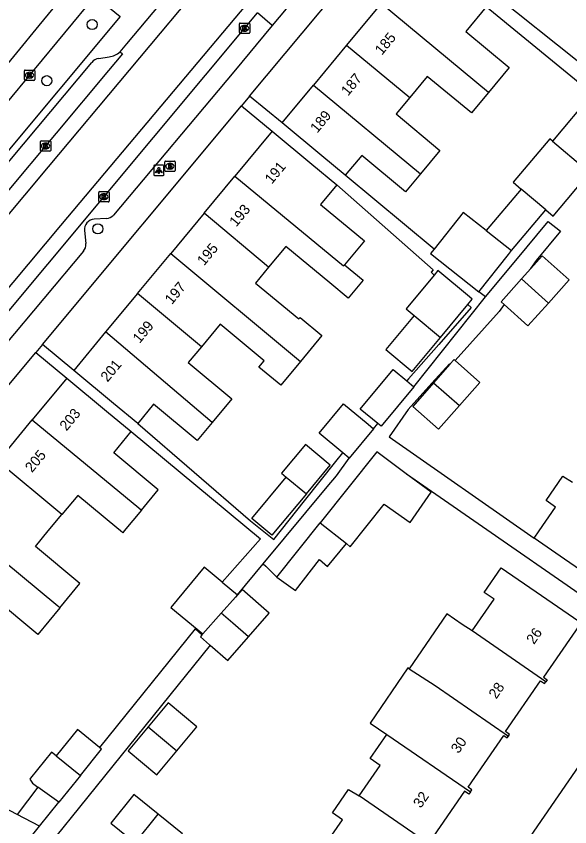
# Model space of a CAD drawing. Extents: x 160158 to 160921, y 381517 to 382041.
# Drawn here: x 160578.4 to 160631.9, y 381721.4 to 381799.8 of the extents above; entities that cross this region are included whole.
import ezdxf

# ---------------------------------------------------------------- set-up
doc = ezdxf.new("R2010")
doc.units = 0
for name, color, linetype in [('IMGEO_Boom', 7, 'Continuous'), ('IMGEO_Brandkraan', 7, 'Continuous'), ('IMGEO_Kolk', 7, 'Continuous'), ('IMGEO_Lichtpunt', 7, 'Continuous'), ('IMGEO_Pand', 7, 'Continuous'), ('IMGEO_Pand_nummerreeks', 7, 'Continuous'), ('IMGEO_Parkeervlak_open', 7, 'Continuous'), ('IMGEO_Rijbaan_lokaal_gesloten', 7, 'Continuous'), ('IMGEO_Voetpad_open', 7, 'Continuous')]:
    doc.layers.add(name, color=color, linetype=linetype)

msp = doc.modelspace()

# ---------------------------------------------------------------- linework, layer by layer
at = {"layer": 'IMGEO_Boom'}
for centre in [(160585.761, 381798.965), (160581.372, 381793.54), (160586.31, 381779.217)]:
    msp.add_circle(centre, 0.489, dxfattribs=at)
at = {"layer": 'IMGEO_Brandkraan'}
for p, q in [((160592.78, 381784.848), (160592.78, 381785.7)), ((160592.855, 381785.774), (160593.707, 381785.774)), ((160593.781, 381785.7), (160593.781, 381784.848)), ((160593.291, 381784.994), (160593.266, 381784.994)), ((160593.268, 381785.554), (160593.293, 381785.554)), ((160593.707, 381784.774), (160592.855, 381784.774))]:
    msp.add_line(p, q, dxfattribs=at)
for points in [[(160592.78, 381784.848), (160592.78, 381785.7)], [(160592.855, 381785.774), (160593.707, 381785.774)], [(160593.781, 381785.7), (160593.781, 381784.848)], [(160593.128, 381785.474), (160593.128, 381785.074), (160593.341, 381785.074)], [(160593.359, 381785.474), (160593.128, 381785.474)], [(160593.307, 381785.393), (160593.253, 381785.393), (160593.253, 381785.317)], [(160593.253, 381785.317), (160593.306, 381785.317)], [(160593.315, 381785.241), (160593.253, 381785.241), (160593.253, 381785.16)], [(160593.253, 381785.16), (160593.315, 381785.16)], [(160593.707, 381784.774), (160592.855, 381784.774)]]:
    msp.add_lwpolyline(points, dxfattribs=at)
for centre, radius, start, end in [((160592.857, 381785.698), 0.0765, 91.55205, 178.44795), ((160592.857, 381785.698), 0.0765, 91.55205, 178.44795), ((160593.705, 381785.698), 0.0765, 1.55205, 88.44795), ((160593.705, 381785.698), 0.0765, 1.55205, 88.44795), ((160592.857, 381784.85), 0.0765, 181.55205, 268.44795), ((160592.857, 381784.85), 0.0765, 181.55205, 268.44795), ((160593.308, 381785.355), 0.0379, 267.82845, 90.93552), ((160593.316, 381785.2), 0.0404, 269.87594, 90.50774), ((160593.347, 381785.325), 0.251, 268.66757, 293.53466), ((160593.363, 381785.329), 0.145, 59.4692, 91.53667), ((160593.388, 381785.376), 0.0922, 285.51372, 58.15012), ((160593.393, 381785.184), 0.105, 301.31148, 78.98903), ((160593.705, 381784.85), 0.0765, 271.55205, 358.44795), ((160593.705, 381784.85), 0.0765, 271.55205, 358.44795)]:
    msp.add_arc(centre, radius, start, end, dxfattribs=at)
for centre, major_axis, ratio, start_param, end_param in [((160593.267, 381785.274), (-0.387, 0.002), 0.722429, 4.712389, 7.853982), ((160593.292, 381785.274), (-0.39, 0.002), 0.717154, 1.570796, 4.712389)]:
    msp.add_ellipse(centre, major_axis=major_axis, ratio=ratio, start_param=start_param, end_param=end_param, dxfattribs=at)
at = {"layer": 'IMGEO_Kolk'}
for p, q in [((160599.992, 381798.185), (160599.992, 381799.037)), ((160600.067, 381799.111), (160600.919, 381799.111)), ((160600.993, 381799.037), (160600.993, 381798.185)), ((160600.503, 381798.331), (160600.478, 381798.331)), ((160600.48, 381798.891), (160600.505, 381798.891)), ((160600.919, 381798.111), (160600.067, 381798.111)), ((160579.208, 381793.647), (160579.208, 381794.499)), ((160579.283, 381794.573), (160580.135, 381794.573)), ((160579.696, 381794.353), (160579.721, 381794.353)), ((160580.209, 381794.499), (160580.209, 381793.647)), ((160580.135, 381793.573), (160579.283, 381793.573)), ((160579.719, 381793.793), (160579.694, 381793.793)), ((160580.754, 381786.801), (160580.754, 381787.653)), ((160580.829, 381787.727), (160581.681, 381787.727)), ((160581.242, 381787.507), (160581.267, 381787.507)), ((160581.755, 381787.653), (160581.755, 381786.801)), ((160581.681, 381786.727), (160580.829, 381786.727)), ((160581.265, 381786.947), (160581.24, 381786.947)), ((160586.393, 381781.89), (160586.393, 381782.742)), ((160586.468, 381782.816), (160587.32, 381782.816)), ((160586.881, 381782.596), (160586.906, 381782.596)), ((160587.394, 381782.742), (160587.394, 381781.89)), ((160587.32, 381781.816), (160586.468, 381781.816)), ((160586.904, 381782.036), (160586.879, 381782.036))]:
    msp.add_line(p, q, dxfattribs=at)
for points in [[(160599.992, 381798.185), (160599.992, 381799.037)], [(160600.067, 381799.111), (160600.919, 381799.111)], [(160600.993, 381799.037), (160600.993, 381798.185)], [(160600.313, 381798.811), (160600.436, 381798.811), (160600.436, 381798.66), (160600.566, 381798.811), (160600.73, 381798.811), (160600.584, 381798.66), (160600.737, 381798.411), (160600.585, 381798.411), (160600.5, 381798.575), (160600.436, 381798.508), (160600.436, 381798.411), (160600.313, 381798.411), (160600.313, 381798.811)], [(160600.919, 381798.111), (160600.067, 381798.111)], [(160579.208, 381793.647), (160579.208, 381794.499)], [(160579.283, 381794.573), (160580.135, 381794.573)], [(160579.529, 381794.273), (160579.652, 381794.273), (160579.652, 381794.122), (160579.782, 381794.273), (160579.946, 381794.273), (160579.8, 381794.122), (160579.953, 381793.873), (160579.801, 381793.873), (160579.716, 381794.037), (160579.652, 381793.97), (160579.652, 381793.873), (160579.529, 381793.873), (160579.529, 381794.273)], [(160580.209, 381794.499), (160580.209, 381793.647)], [(160580.135, 381793.573), (160579.283, 381793.573)], [(160580.754, 381786.801), (160580.754, 381787.653)], [(160580.829, 381787.727), (160581.681, 381787.727)], [(160581.075, 381787.427), (160581.198, 381787.427), (160581.198, 381787.276), (160581.328, 381787.427), (160581.492, 381787.427), (160581.346, 381787.276), (160581.499, 381787.027), (160581.347, 381787.027), (160581.262, 381787.191), (160581.198, 381787.124), (160581.198, 381787.027), (160581.075, 381787.027), (160581.075, 381787.427)], [(160581.755, 381787.653), (160581.755, 381786.801)], [(160581.681, 381786.727), (160580.829, 381786.727)], [(160586.393, 381781.89), (160586.393, 381782.742)], [(160586.468, 381782.816), (160587.32, 381782.816)], [(160586.714, 381782.516), (160586.837, 381782.516), (160586.837, 381782.365), (160586.967, 381782.516), (160587.131, 381782.516), (160586.985, 381782.365), (160587.138, 381782.116), (160586.986, 381782.116), (160586.901, 381782.28), (160586.837, 381782.213), (160586.837, 381782.116), (160586.714, 381782.116), (160586.714, 381782.516)], [(160587.394, 381782.742), (160587.394, 381781.89)], [(160587.32, 381781.816), (160586.468, 381781.816)]]:
    msp.add_lwpolyline(points, dxfattribs=at)
for centre, start, end in [((160600.069, 381799.035), 91.55205, 178.44795), ((160600.069, 381799.035), 91.55205, 178.44795), ((160600.917, 381799.035), 1.55205, 88.44795), ((160600.917, 381799.035), 1.55205, 88.44795), ((160600.069, 381798.187), 181.55205, 268.44795), ((160600.069, 381798.187), 181.55205, 268.44795), ((160600.917, 381798.187), 271.55205, 358.44795), ((160600.917, 381798.187), 271.55205, 358.44795), ((160579.285, 381794.497), 91.55205, 178.44795), ((160579.285, 381794.497), 91.55205, 178.44795), ((160580.133, 381794.497), 1.55205, 88.44795), ((160580.133, 381794.497), 1.55205, 88.44795), ((160579.285, 381793.649), 181.55205, 268.44795), ((160579.285, 381793.649), 181.55205, 268.44795), ((160580.133, 381793.649), 271.55205, 358.44795), ((160580.133, 381793.649), 271.55205, 358.44795), ((160580.831, 381787.651), 91.55205, 178.44795), ((160580.831, 381787.651), 91.55205, 178.44795), ((160581.679, 381787.651), 1.55205, 88.44795), ((160581.679, 381787.651), 1.55205, 88.44795), ((160580.831, 381786.803), 181.55205, 268.44795), ((160580.831, 381786.803), 181.55205, 268.44795), ((160581.679, 381786.803), 271.55205, 358.44795), ((160581.679, 381786.803), 271.55205, 358.44795), ((160586.47, 381782.74), 91.55205, 178.44795), ((160586.47, 381782.74), 91.55205, 178.44795), ((160587.318, 381782.74), 1.55205, 88.44795), ((160587.318, 381782.74), 1.55205, 88.44795), ((160586.47, 381781.892), 181.55205, 268.44795), ((160586.47, 381781.892), 181.55205, 268.44795), ((160587.318, 381781.892), 271.55205, 358.44795), ((160587.318, 381781.892), 271.55205, 358.44795)]:
    msp.add_arc(centre, 0.0765, start, end, dxfattribs=at)
for centre, major_axis, ratio, start_param, end_param in [((160600.479, 381798.611), (-0.387, 0.002), 0.722429, 4.712389, 7.853982), ((160600.504, 381798.611), (-0.39, 0.002), 0.717154, 1.570796, 4.712389), ((160579.695, 381794.073), (-0.387, 0.002), 0.722429, 4.712389, 7.853982), ((160579.72, 381794.073), (-0.39, 0.002), 0.717154, 1.570796, 4.712389), ((160581.241, 381787.227), (-0.387, 0.002), 0.722429, 4.712389, 7.853982), ((160581.266, 381787.227), (-0.39, 0.002), 0.717154, 1.570796, 4.712389), ((160586.88, 381782.316), (-0.387, 0.002), 0.722429, 4.712389, 7.853982), ((160586.905, 381782.316), (-0.39, 0.002), 0.717154, 1.570796, 4.712389)]:
    msp.add_ellipse(centre, major_axis=major_axis, ratio=ratio, start_param=start_param, end_param=end_param, dxfattribs=at)
at = {"layer": 'IMGEO_Lichtpunt'}
for p, q in [((160591.708, 381785.265), (160591.708, 381784.458)), ((160591.708, 381785.265), (160591.708, 381784.458)), ((160592.61, 381785.36), (160591.802, 381785.36)), ((160592.61, 381785.36), (160591.802, 381785.36)), ((160592.704, 381784.458), (160592.704, 381785.265)), ((160592.704, 381784.458), (160592.704, 381785.265)), ((160591.802, 381784.364), (160592.61, 381784.364)), ((160591.802, 381784.364), (160592.61, 381784.364))]:
    msp.add_line(p, q, dxfattribs=at)
for points in [[(160592.082, 381784.929), (160592.121, 381784.901), (160591.933, 381784.639), (160591.895, 381784.666), (160592.082, 381784.929)], [(160592.184, 381784.881), (160592.231, 381784.881), (160592.231, 381784.559), (160592.184, 381784.559), (160592.184, 381784.881)], [(160592.294, 381784.901), (160592.332, 381784.928), (160592.519, 381784.666), (160592.48, 381784.638), (160592.294, 381784.901)]]:
    msp.add_lwpolyline(points, dxfattribs=at)
msp.add_circle((160592.207, 381785.063), 0.0994, dxfattribs=at)
for centre, start, end in [((160591.802, 381785.265), 90, 180), ((160591.802, 381785.265), 90, 180), ((160592.61, 381785.265), 0, 90), ((160592.61, 381785.265), 0, 90), ((160591.802, 381784.458), 180, 270), ((160591.802, 381784.458), 180, 270), ((160592.61, 381784.458), 270, 0), ((160592.61, 381784.458), 270, 360)]:
    msp.add_arc(centre, 0.0946, start, end, dxfattribs=at)
at = {"layer": 'IMGEO_Pand'}
for points in [[(160613.699, 381801.016), (160610.355, 381796.984)], [(160624.054, 381792.414), (160613.699, 381801.016)], [(160623.85, 381800.698), (160621.866, 381798.306), (160626.058, 381794.831), (160624.054, 381792.414)], [(160610.355, 381796.984), (160607.145, 381793.112)], [(160610.355, 381796.984), (160616.457, 381791.914)], [(160624.054, 381792.414), (160622.407, 381790.428), (160618.151, 381793.957), (160616.457, 381791.914)], [(160604.113, 381789.456), (160607.145, 381793.112)], [(160607.145, 381793.112), (160617.48, 381784.519)], [(160616.457, 381791.914), (160615.136, 381790.321), (160619.376, 381786.805), (160617.48, 381784.519)], [(160636.267, 381787.531), (160637.69, 381789.221), (160637.509, 381789.373), (160634.08, 381792.26), (160630.243, 381787.704)], [(160610.22, 381784.393), (160607.963, 381786.265), (160604.113, 381789.456)], [(160603.149, 381788.654), (160599.546, 381784.309)], [(160603.149, 381788.654), (160606.998, 381785.462), (160609.411, 381783.461)], [(160630.243, 381787.704), (160629.985, 381787.921), (160626.441, 381783.713), (160627.218, 381783.059)], [(160630.243, 381787.704), (160633.38, 381785.062), (160633.672, 381784.816), (160633.853, 381784.664)], [(160617.48, 381784.519), (160616.05, 381782.795), (160611.81, 381786.311), (160610.22, 381784.393)], [(160596.578, 381780.729), (160599.546, 381784.309)], [(160599.546, 381784.309), (160610.066, 381775.629), (160610.147, 381775.727)], [(160629.603, 381781.05), (160630.309, 381780.456), (160633.853, 381784.664)], [(160609.411, 381783.461), (160607.831, 381781.555), (160612.067, 381778.042), (160610.147, 381775.727)], [(160627.218, 381783.059), (160623.836, 381779.042)], [(160629.603, 381781.05), (160627.218, 381783.059)], [(160626.281, 381777.105), (160629.603, 381781.05)], [(160596.578, 381780.729), (160593.35, 381776.836)], [(160602.819, 381775.504), (160596.578, 381780.729)], [(160623.836, 381779.042), (160621.617, 381780.799), (160618.818, 381777.265)], [(160623.836, 381779.042), (160626.281, 381777.105)], [(160610.147, 381775.727), (160611.944, 381774.237), (160610.517, 381772.516), (160608.72, 381774.006), (160604.488, 381777.515), (160602.819, 381775.504)], [(160618.818, 381777.265), (160618.471, 381776.827), (160623.135, 381773.133)], [(160623.135, 381773.133), (160625.982, 381776.728), (160626.281, 381777.105)], [(160590.132, 381772.955), (160593.35, 381776.836)], [(160593.35, 381776.836), (160605.905, 381766.397)], [(160629.85, 381772.044), (160631.853, 381774.294), (160629.249, 381776.614), (160628.141, 381775.37)], [(160602.819, 381775.504), (160601.549, 381773.972), (160605.73, 381770.505), (160605.848, 381770.647), (160607.97, 381768.888), (160605.905, 381766.397)], [(160618.828, 381774.748), (160616.108, 381771.469), (160616.872, 381770.836)], [(160622.062, 381771.895), (160622.499, 381772.422), (160622.243, 381772.634), (160619.181, 381775.174), (160618.828, 381774.748)], [(160628.141, 381775.37), (160627.252, 381774.372)], [(160627.252, 381774.372), (160625.274, 381772.152), (160625.571, 381771.888)], [(160627.252, 381774.372), (160629.85, 381772.044)], [(160590.132, 381772.955), (160587.056, 381769.246)], [(160596.317, 381767.811), (160590.132, 381772.955)], [(160619.426, 381768.717), (160622.062, 381771.895)], [(160625.571, 381771.888), (160627.878, 381769.832), (160629.85, 381772.044)], [(160616.872, 381770.836), (160614.146, 381767.549), (160616.7, 381765.431), (160619.426, 381768.717)], [(160616.872, 381770.836), (160619.426, 381768.717)], [(160605.905, 381766.397), (160603.993, 381764.091), (160601.871, 381765.85), (160602.376, 381766.46), (160598.122, 381769.987), (160596.317, 381767.811)], [(160587.056, 381769.246), (160583.975, 381765.53)], [(160597.366, 381760.495), (160587.056, 381769.246)], [(160596.317, 381767.811), (160595.053, 381766.287), (160599.27, 381762.79), (160597.366, 381760.495)], [(160620.344, 381766.121), (160618.76, 381764.325)], [(160620.836, 381766.477), (160620.736, 381766.565), (160620.344, 381766.121)], [(160621.247, 381762.13), (160623.224, 381764.369), (160620.836, 381766.477)], [(160590.16, 381760.402), (160587.824, 381762.338), (160583.975, 381765.53)], [(160613.371, 381760.384), (160611.674, 381761.791), (160614.845, 381765.615), (160616.162, 381764.523)], [(160583.302, 381764.776), (160579.972, 381760.755)], [(160583.302, 381764.776), (160587.153, 381761.587), (160589.547, 381759.605)], [(160616.162, 381764.523), (160616.856, 381763.947)], [(160616.856, 381763.947), (160613.685, 381760.124), (160613.371, 381760.384)], [(160618.76, 381764.325), (160616.748, 381762.046), (160619.236, 381759.85), (160621.247, 381762.13)], [(160618.76, 381764.325), (160621.247, 381762.13)], [(160597.366, 381760.495), (160595.915, 381758.745), (160591.69, 381762.248), (160590.16, 381760.402)], [(160609.995, 381757.547), (160607.702, 381759.449), (160610.051, 381762.283), (160612.423, 381760.316), (160612.949, 381759.88)], [(160576.632, 381756.722), (160579.972, 381760.755)], [(160579.972, 381760.755), (160590.276, 381752.222), (160590.52, 381752.009)], [(160612.949, 381759.88), (160610.599, 381757.047)], [(160590.52, 381752.009), (160592.153, 381753.981), (160587.844, 381757.549), (160589.547, 381759.605)], [(160606.465, 381753.593), (160608.762, 381756.361), (160606.364, 381758.351), (160604.067, 381755.582), (160604.512, 381755.213)], [(160616.12, 381755.522), (160613.268, 381757.641), (160607.805, 381750.8)], [(160610.599, 381757.047), (160609.995, 381757.547)], [(160582.827, 381751.583), (160582.646, 381751.741), (160576.632, 381756.722)], [(160606.465, 381753.593), (160603.141, 381749.585), (160601.187, 381751.206), (160604.512, 381755.213)], [(160604.512, 381755.213), (160606.465, 381753.593)], [(160610.343, 381748.774), (160610.71, 381748.48), (160613.986, 381752.582), (160616.51, 381750.829), (160618.513, 381753.744), (160616.12, 381755.522)], [(160628.466, 381749.29), (160628.963, 381750.012), (160630.547, 381752.316), (160629.632, 381752.945), (160631.262, 381755.314), (160632.183, 381754.723)], [(160590.52, 381752.009), (160588.859, 381750.003), (160588.717, 381749.831), (160588.514, 381750), (160588.154, 381750.298), (160584.361, 381753.438), (160582.827, 381751.583)], [(160582.629, 381742.571), (160580.503, 381740.004), (160576.203, 381743.565), (160574.337, 381741.312), (160571.979, 381743.266), (160568.128, 381746.455), (160571.065, 381750), (160572.125, 381751.28)], [(160572.125, 381751.28), (160573.671, 381750), (160582.428, 381742.749), (160582.629, 381742.571)], [(160582.629, 381742.571), (160584.581, 381744.929), (160580.272, 381748.497), (160581.517, 381750), (160582.827, 381751.583)], [(160603.608, 381745.544), (160607.805, 381750.8)], [(160607.805, 381750.8), (160610.343, 381748.774)], [(160635.527, 381744.43), (160631.409, 381747.265), (160628.466, 381749.29)], [(160603.608, 381745.544), (160605.42, 381744.24), (160607.742, 381747.227), (160608.494, 381746.575), (160610.343, 381748.774)], [(160598.332, 381745.061), (160596.585, 381746.507), (160593.359, 381742.611), (160596.461, 381740.042)], [(160622.489, 381740.337), (160624.606, 381743.402), (160623.645, 381744.065), (160625.288, 381746.445), (160629.186, 381743.753), (160633.3, 381740.911), (160633.12, 381740.65), (160632.827, 381740.852), (160629.378, 381735.858), (160629.734, 381735.612), (160629.605, 381735.425)], [(160598.332, 381745.061), (160599.806, 381743.839)], [(160600.862, 381739.755), (160602.861, 381742.048), (160600.249, 381744.326), (160599.814, 381743.833)], [(160599.814, 381743.833), (160599.603, 381743.595), (160598.234, 381742.047)], [(160599.814, 381743.833), (160599.806, 381743.839)], [(160598.234, 381742.047), (160596.461, 381740.042)], [(160600.862, 381739.755), (160599.347, 381741.076), (160598.234, 381742.047)], [(160622.489, 381740.337), (160621.524, 381740.968), (160620.053, 381741.983), (160616.394, 381736.683)], [(160629.605, 381735.425), (160622.489, 381740.337)], [(160596.374, 381739.944), (160596.236, 381739.752), (160597.095, 381739.003), (160597.155, 381738.951)], [(160596.461, 381740.042), (160596.374, 381739.944)], [(160597.155, 381738.951), (160598.863, 381737.462), (160600.862, 381739.755)], [(160616.394, 381736.683), (160616.276, 381736.763), (160612.644, 381731.403), (160614.228, 381730.33)], [(160616.394, 381736.683), (160618.902, 381735.062), (160625.992, 381730.168)], [(160625.992, 381730.168), (160626.105, 381730.332), (160625.702, 381730.61), (160629.085, 381735.508), (160629.476, 381735.239), (160629.605, 381735.425)], [(160593.94, 381728.749), (160595.882, 381731.073), (160593.122, 381733.379), (160591.18, 381731.055)], [(160586.466, 381729.064), (160584.338, 381730.8), (160582.267, 381728.261)], [(160591.18, 381731.055), (160589.238, 381728.731), (160591.998, 381726.425), (160593.94, 381728.749)], [(160591.18, 381731.055), (160593.94, 381728.749)], [(160611.566, 381724.39), (160613.595, 381727.326), (160612.619, 381728), (160614.228, 381730.33)], [(160614.228, 381730.33), (160622.316, 381724.76)], [(160622.316, 381724.76), (160622.467, 381724.978), (160622.093, 381725.237), (160625.546, 381730.236), (160625.88, 381730.005), (160625.992, 381730.168)], [(160582.267, 381728.261), (160581.832, 381728.616), (160579.814, 381726.109), (160579.725, 381725.998), (160579.982, 381725.625), (160580.517, 381725.236)], [(160584.62, 381726.346), (160586.673, 381728.895), (160586.466, 381729.064)], [(160582.267, 381728.261), (160584.62, 381726.346)], [(160584.62, 381726.346), (160582.54, 381723.763)], [(160578.499, 381722.589), (160577.825, 381722.945), (160575.47, 381724.12), (160573.871, 381725.087), (160572.609, 381725.146), (160572.635, 381725.69)], [(160580.517, 381725.236), (160578.499, 381722.589)], [(160582.54, 381723.763), (160580.517, 381725.236)], [(160592.15, 381722.608), (160589.796, 381724.503), (160587.578, 381721.747), (160589.931, 381719.852)], [(160607.906, 381719.099), (160609.95, 381722.059), (160608.978, 381722.731), (160610.55, 381725.008), (160611.566, 381724.39)], [(160622.316, 381724.76), (160622.167, 381724.544), (160621.759, 381724.825), (160618.405, 381719.969), (160618.774, 381719.715), (160618.634, 381719.512)], [(160580.671, 381721.44), (160582.54, 381723.763)], [(160618.634, 381719.512), (160611.566, 381724.39)], [(160580.671, 381721.44), (160578.499, 381722.589)], [(160589.931, 381719.852), (160592.15, 381722.608)], [(160589.931, 381719.852), (160592.285, 381717.957), (160594.504, 381720.713), (160592.15, 381722.608)], [(160573.979, 381713.128), (160577.115, 381717.023), (160580.671, 381721.44)]]:
    msp.add_lwpolyline(points, dxfattribs=at)
at = {"layer": 'IMGEO_Parkeervlak_open'}
msp.add_lwpolyline([(160603.167, 381798.883), (160601.731, 381800.097)], dxfattribs=at)
at = {"layer": 'IMGEO_Rijbaan_lokaal_gesloten'}
for points in [[(160588.465, 381796.32), (160589.126, 381797.112), (160595.401, 381804.621), (160595.807, 381805.107)], [(160556.164, 381754.68), (160558.112, 381757.129), (160560.755, 381760.365), (160581.539, 381785.212), (160597.19, 381803.934)], [(160600.729, 381800.991), (160582.713, 381779.526), (160568.843, 381763.002), (160559.601, 381751.709)], [(160559.501, 381749.238), (160560.113, 381750), (160567.175, 381758.693), (160571.401, 381763.753), (160601.731, 381800.097)], [(160588.465, 381796.32), (160588.699, 381796.124), (160587.352, 381794.513), (160562.011, 381764.214)]]:
    msp.add_lwpolyline(points, dxfattribs=at)
at = {"layer": 'IMGEO_Voetpad_open'}
for points in [[(160600.981, 381792.054), (160614.597, 381808.384)], [(160587.941, 381807.827), (160580.593, 381798.887), (160569.786, 381785.666)], [(160609.261, 381806.17), (160603.167, 381798.883)], [(160648.718, 381802.7), (160643.768, 381797.021), (160642.365, 381795.237), (160640.014, 381792.247), (160637.708, 381789.314), (160623.85, 381800.698)], [(160588.465, 381799.75), (160576.606, 381785.578), (160574.286, 381787.517), (160586.055, 381801.74), (160588.465, 381799.75)], [(160624.886, 381801.729), (160632.65, 381795.49)], [(160603.167, 381798.883), (160599.457, 381794.39), (160587.813, 381780.546)], [(160586.397, 381795.685), (160587.396, 381795.843)], [(160562.514, 381767.661), (160568.354, 381774.575), (160585.728, 381795.315)], [(160600.981, 381792.054), (160600.191, 381791.107)], [(160604.113, 381789.456), (160600.981, 381792.054)], [(160580.96, 381768.044), (160600.191, 381791.107)], [(160600.191, 381791.107), (160603.149, 381788.654)], [(160618.818, 381777.265), (160610.22, 381784.393)], [(160609.411, 381783.461), (160618.724, 381775.25), (160618.52, 381775.019), (160618.828, 381774.748)], [(160587.135, 381780.202), (160585.959, 381780.139)], [(160623.764, 381772.635), (160626.697, 381776.162), (160629.831, 381779.931), (160631.029, 381778.982), (160628.664, 381776.14), (160628.117, 381775.388), (160628.141, 381775.37)], [(160585.037, 381779.048), (160585.151, 381777.783)], [(160584.925, 381777.042), (160573.379, 381763.328)], [(160623.764, 381772.635), (160623.135, 381773.133)], [(160616.856, 381763.947), (160623.764, 381772.635)], [(160622.062, 381771.895), (160622.405, 381771.593), (160619.268, 381768.036), (160616.34, 381764.716), (160616.162, 381764.523)], [(160625.571, 381771.888), (160625.081, 381771.214), (160620.836, 381766.477)], [(160580.96, 381768.044), (160580.313, 381767.268)], [(160583.975, 381765.53), (160580.96, 381768.044)], [(160561.169, 381743.908), (160564.062, 381747.78), (160565.914, 381750), (160580.313, 381767.268)], [(160580.313, 381767.268), (160583.302, 381764.776)], [(160620.344, 381766.121), (160620.286, 381766.173), (160618.59, 381764.28), (160616.315, 381761.741), (160614.463, 381759.095), (160628.466, 381749.29)], [(160590.16, 381760.402), (160601.066, 381750.975), (160603.33, 381749.176), (160606.298, 381752.913), (160607.809, 381754.815), (160609.32, 381756.717), (160609.995, 381757.547)], [(160612.949, 381759.88), (160613.371, 381760.384)], [(160589.547, 381759.605), (160602.042, 381749.255), (160598.332, 381745.061)], [(160602.288, 381746.821), (160608.487, 381754.269), (160609.371, 381755.332), (160610.599, 381757.047)], [(160616.12, 381755.522), (160616.134, 381755.539), (160640.592, 381738.561)], [(160599.806, 381743.839), (160602.288, 381746.821)], [(160602.288, 381746.821), (160602.546, 381746.607), (160603.608, 381745.544)], [(160596.374, 381739.944), (160595.702, 381740.538), (160586.466, 381729.064)], [(160597.155, 381738.951), (160580.648, 381718.45)], [(160605.905, 381688.17), (160640.592, 381738.561)]]:
    msp.add_lwpolyline(points, dxfattribs=at)
for centre, radius, start, end in [((160587.102, 381797.938), 2.115, 277.98168, 310.11227), ((160586.499, 381794.711), 0.98, 95.97854, 141.91229), ((160586, 381779.169), 0.971, 92.43427, 187.16368), ((160587.048, 381781.214), 1.016, 274.9318, 318.87236), ((160584.106, 381777.697), 1.048, 321.35503, 4.72227)]:
    msp.add_arc(centre, radius, start, end, dxfattribs=at)

# ---------------------------------------------------------------- texts
at = {"layer": 'IMGEO_Pand_nummerreeks'}
for s, rotation, p in [('185', 50.33423, (160613.763, 381795.956)), ('187', 50.33423, (160610.486, 381792.004)), ('189', 50.33423, (160607.511, 381788.417)), ('191', 50.33509, (160603.123, 381783.484)), ('193', 50.33509, (160599.691, 381779.347)), ('195', 50.33509, (160596.577, 381775.591)), ('197', 50.33509, (160593.463, 381771.835)), ('199', 50.33509, (160590.349, 381768.08)), ('201', 50.33509, (160587.248, 381764.341)), ('203', 50.36956, (160583.284, 381759.612)), ('205', 50.36956, (160579.949, 381755.585)), ('26', 55.35651, (160628.46, 381738.967)), ('28', 55.35918, (160624.817, 381733.692)), ('30', 55.35918, (160621.171, 381728.415)), ('32', 55.35651, (160617.522, 381723.135))]:
    msp.add_text(s, height=1, rotation=rotation, dxfattribs=at).set_placement(p)

doc.saveas('drawing.dxf')
